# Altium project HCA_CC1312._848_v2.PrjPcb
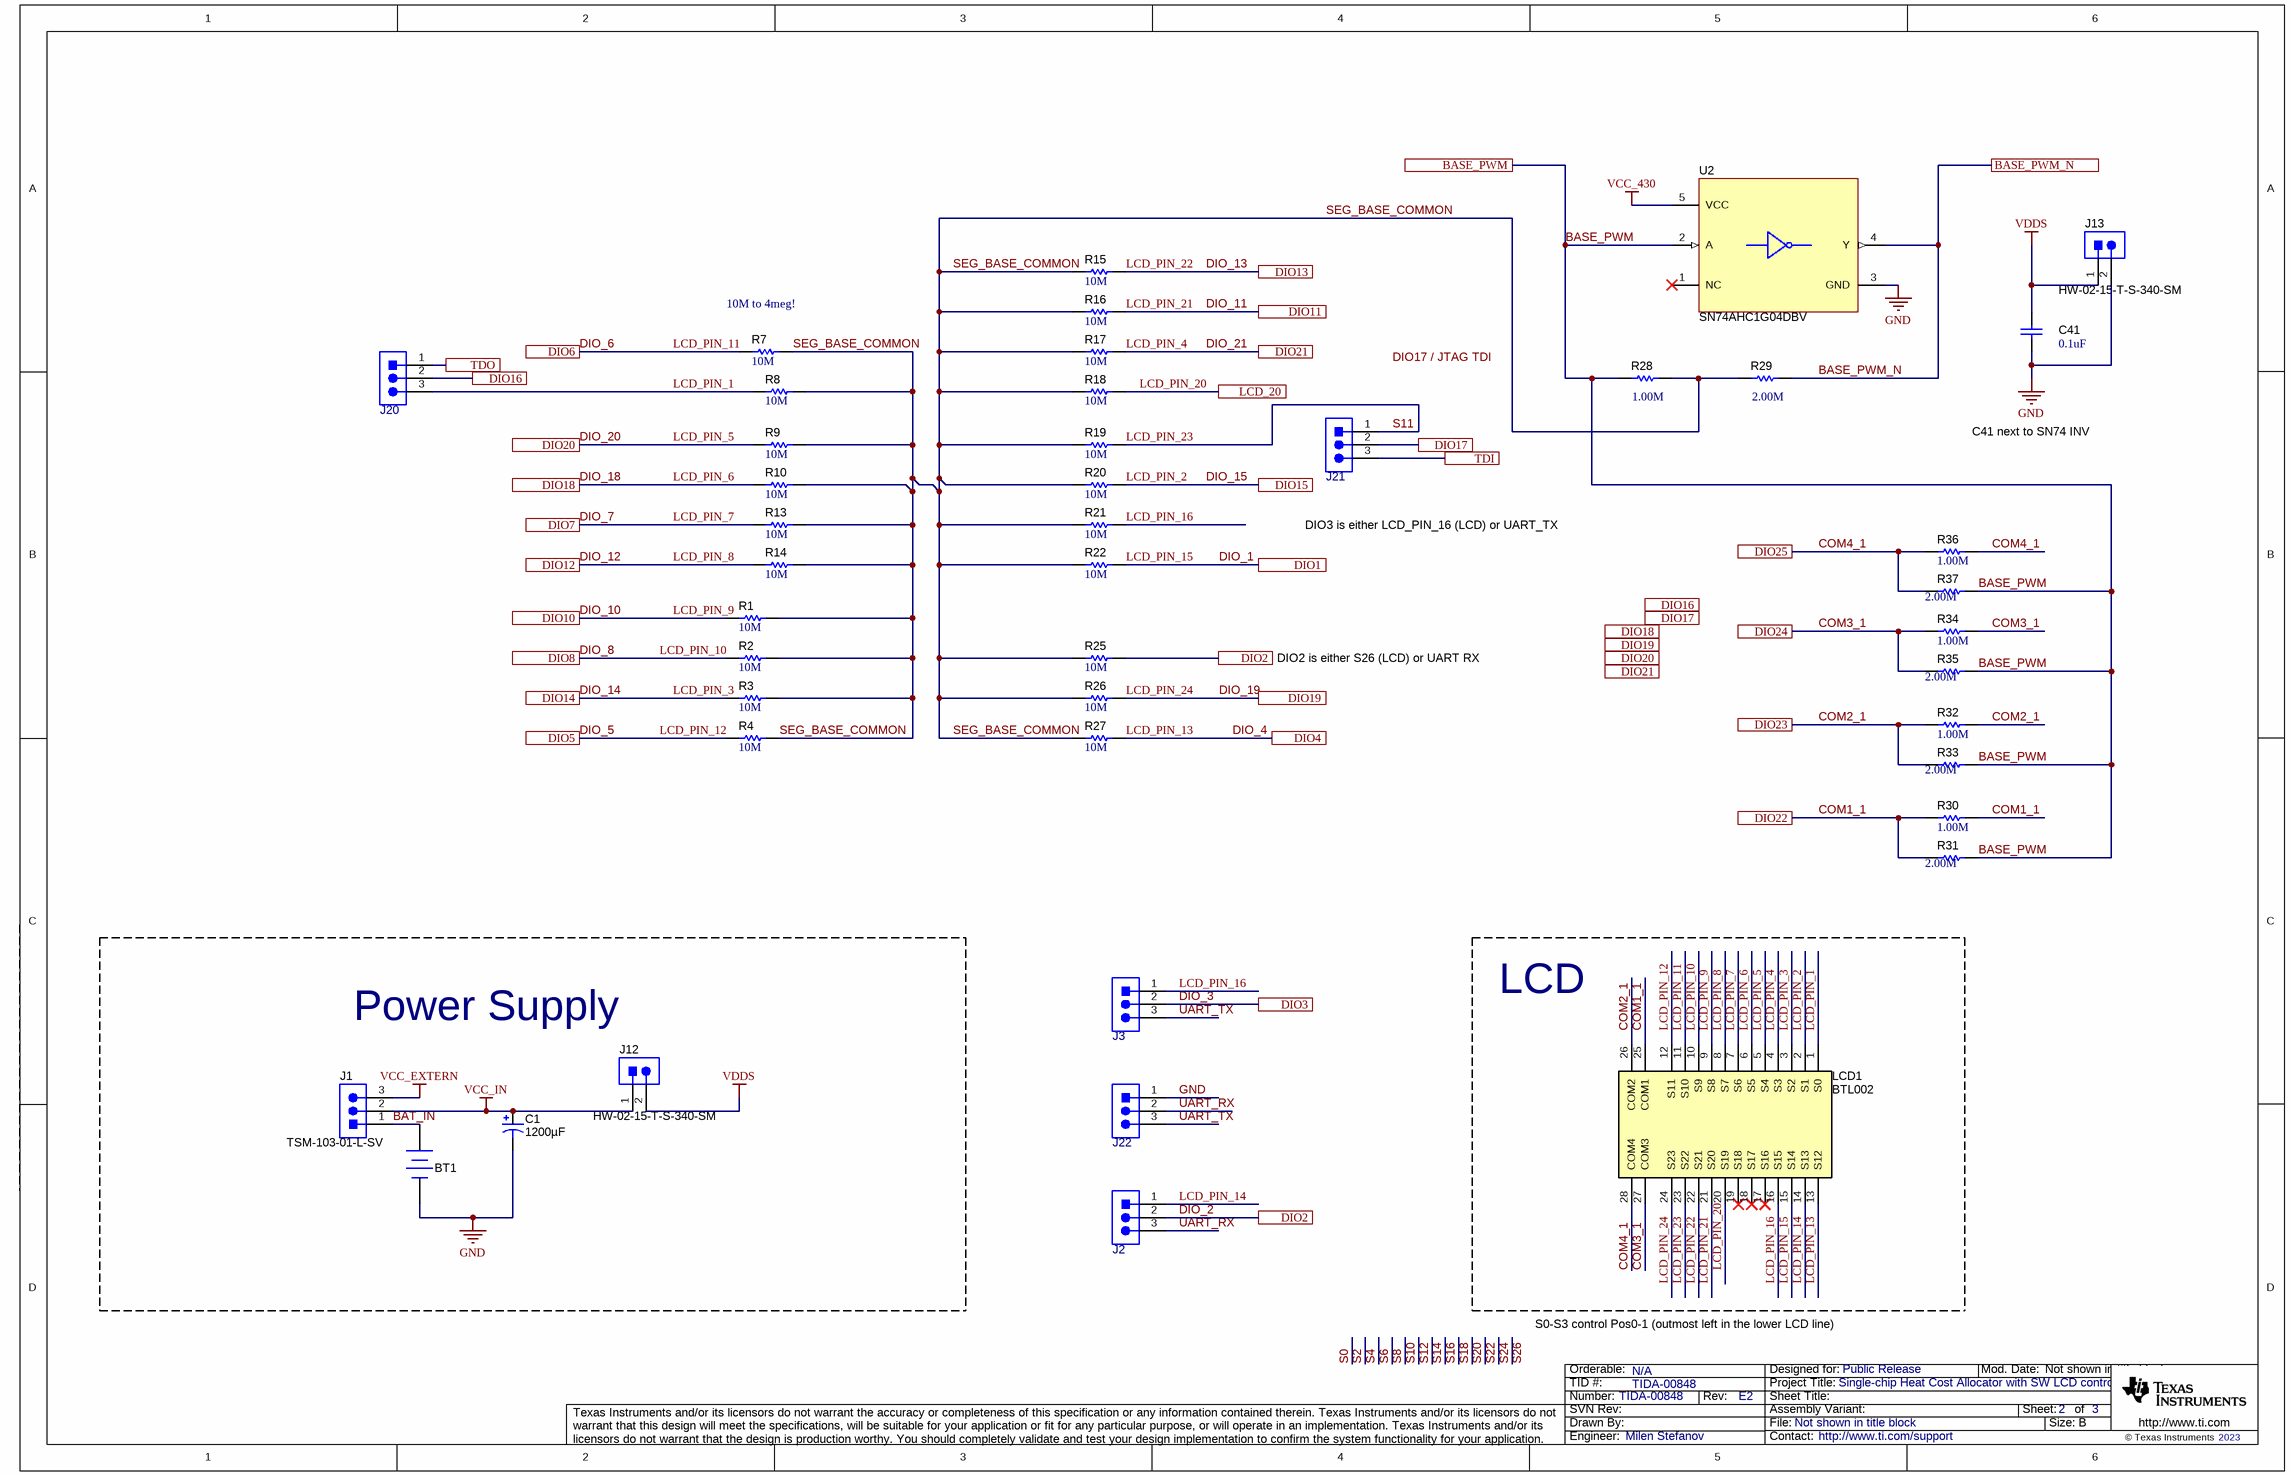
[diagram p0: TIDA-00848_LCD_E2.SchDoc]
CopyrightYear: 2023; EVM_Orderable: N/A; PCB_Layout: Milen Stefanov; PCB_Rev: E2; PRJ_Customer: Public Release; PRJ_Engineer: Milen Stefanov; PRJ_Number: TIDA-00848; PRJ_Title: Single-chip Heat Cost Allocator with SW LCD control; SCH_Rev: E2; TechSupport: http://www.ti.com/support; TID: TIDA-00848
4 sheets, 102 parts. Net scope: flat (ports and power ports of the same name join across sheets).
Board file: TIDA-00848_E2.PcbDoc
Sheets:
  TIDA-00848_LCD_E2.SchDoc
  TIDA-00848__Hardware_E2.SchDoc
  TIDA-00848_RF_E2.SchDoc
  TIDA-00848-CoverSheet_E2.SchDoc

## Sheet TIDA-00848_LCD_E2.SchDoc
size 431 x 279 mm; Date: Not shown in title block; ApprovedBy: Not shown in title block; CheckedBy: Not shown in title block; Author: Not shown in title block; CompanyName: Not shown in title block; Engineer: Not shown in title block; Organization: Not shown in title block; Address1: Not shown in title block; Address2: Not shown in title block; Address3: Not shown in title block; Address4: Not shown in title block; DocumentNumber: 1; Revision: Use project parameter SCH_Rev; SheetNumber: 2; SheetTotal: 3; PageSetup: Record=PageOptions¦CenterHorizontal=True¦CenterVertical=True¦PrintScale=0.62¦XCorrection=1.00¦YCorrection=1.00¦PrintKind=0¦BorderSize=5000000¦LeftOffset=0¦BottomOffset=0¦Orientation=2¦PaperLength=2794¦PaperWidth=2159¦Scale=100¦PaperSource=7¦PrintQuality=600¦MediaType=1¦DitherType=10¦PrintScaleMode=1¦PaperKind=8 1/2x11¦PaperIndex=1

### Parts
BT1  1010  [BAT_1010]  (value not drawn)
C1  ValueDisplayed: 1200µF  [CAPPR5-10X20]  (hidden comment: EEUFM1A122)
C41  ValueDisplayed: 0.1uF  [0402]  (hidden comment: CMP-0006607-2)
J1  TSM-103-01-L-SV  [Samtec_TSM-103-01-X-SV]
J2  TSW-103-07-G-S  [TSW-103-07-G-S]  (value not drawn)
J3  TSW-103-07-G-S  [TSW-103-07-G-S]  (value not drawn)
J12  HW-02-15-T-S-340-SM  [Samtec_HW-02-15-X-S-340-SM]
J13  HW-02-15-T-S-340-SM  [Samtec_HW-02-15-X-S-340-SM]
J20  TSW-103-07-G-S  [TSW-103-07-G-S]  (value not drawn)
J21  TSW-103-07-G-S  [TSW-103-07-G-S]  (value not drawn)
J22  TSW-103-07-G-S  [TSW-103-07-G-S]  (value not drawn)
LCD1  BTL002  [TI_BTL002]
R1  ValueDisplayed: 10M  [0402]  (hidden comment: CMP-0026826-2)
R2  ValueDisplayed: 10M  [0402]  (hidden comment: CMP-0026826-2)
R3  ValueDisplayed: 10M  [0402]  (hidden comment: CMP-0026826-2)
R4  ValueDisplayed: 10M  [0402]  (hidden comment: CMP-0026826-2)
R7  ValueDisplayed: 10M  [0402]  (hidden comment: CMP-0026826-2)
R8  ValueDisplayed: 10M  [0402]  (hidden comment: CMP-0026826-2)
R9  ValueDisplayed: 10M  [0402]  (hidden comment: CMP-0026826-2)
R10  ValueDisplayed: 10M  [0402]  (hidden comment: CMP-0026826-2)
R13  ValueDisplayed: 10M  [0402]  (hidden comment: CMP-0026826-2)
R14  ValueDisplayed: 10M  [0402]  (hidden comment: CMP-0026826-2)
R15  ValueDisplayed: 10M  [0402]  (hidden comment: CMP-0026826-2)
R16  ValueDisplayed: 10M  [0402]  (hidden comment: CMP-0026826-2)
R17  ValueDisplayed: 10M  [0402]  (hidden comment: CMP-0026826-2)
R18  ValueDisplayed: 10M  [0402]  (hidden comment: CMP-0026826-2)
R19  ValueDisplayed: 10M  [0402]  (hidden comment: CMP-0026826-2)
R20  ValueDisplayed: 10M  [0402]  (hidden comment: CMP-0026826-2)
R21  ValueDisplayed: 10M  [0402]  (hidden comment: CMP-0026826-2)
R22  ValueDisplayed: 10M  [0402]  (hidden comment: CMP-0026826-2)
R25  ValueDisplayed: 10M  [0402]  (hidden comment: CMP-0026826-2)
R26  ValueDisplayed: 10M  [0402]  (hidden comment: CMP-0026826-2)
R27  ValueDisplayed: 10M  [0402]  (hidden comment: CMP-0026826-2)
R28  ValueDisplayed: 1.00M  [0402]  (hidden comment: CRCW04021M00FKED)
R29  ValueDisplayed: 2.00M  [0402]  (hidden comment: CRCW04022M00FKED)
R30  ValueDisplayed: 1.00M  [0402S]  (hidden comment: CRCW04021M00FKED)
R31  ValueDisplayed: 2.00M  [0402S]  (hidden comment: CRCW04022M00FKED)
R32  ValueDisplayed: 1.00M  [0402S]  (hidden comment: CRCW04021M00FKED)
R33  ValueDisplayed: 2.00M  [0402S]  (hidden comment: CRCW04022M00FKED)
R34  ValueDisplayed: 1.00M  [0402S]  (hidden comment: CRCW04021M00FKED)
R35  ValueDisplayed: 2.00M  [0402S]  (hidden comment: CRCW04022M00FKED)
R36  ValueDisplayed: 1.00M  [0402S]  (hidden comment: CRCW04021M00FKED)
R37  ValueDisplayed: 2.00M  [0402S]  (hidden comment: CRCW04022M00FKED)
U2  SN74AHC1G04DBV  [DBV0005A_M]

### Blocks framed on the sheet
Power Supply: BT1 C1 J1 J12
LCD: LCD1

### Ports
BASE_PWM, BASE_PWM_N, DIO1, DIO2, DIO3, DIO4, DIO5, DIO6, DIO7, DIO8, DIO10, DIO11, DIO12, DIO13, DIO14, DIO15, DIO16, DIO17, DIO18, DIO19, DIO20, DIO21, DIO22, DIO23, DIO24, DIO25, LCD_20, TDI, TDO

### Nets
GND: BT1.2(-) C1.2(-) C41.2 J13.2 J22.1 U2.3(GND)
VCC_430: U2.5(VCC)
VCC_EXTERN: J1.3
VCC_IN: C1.1(+) J1.2 J12.1
VDDS: C41.1 J12.2 J13.1
BASE_PWM: R28.1 R31.2 R33.2 R35.2 R37.2 U2.2(A) ; port BASE_PWM
BASE_PWM_N: R29.2 U2.4(Y) ; port BASE_PWM_N
BAT_IN: BT1.1(+) J1.1
COM1_1: LCD1.25(COM1) R30.1 R30.2 R31.1 ; port DIO22
COM2_1: LCD1.26(COM2) R32.1 R32.2 R33.1 ; port DIO23
COM3_1: LCD1.27(COM3) R34.1 R34.2 R35.1 ; port DIO24
COM4_1: LCD1.28(COM4) R36.1 R36.2 R37.1 ; port DIO25
DIO_1: LCD1.15(S14) R22.2 ; port DIO1  [also labelled LCD_PIN_15]
DIO_2: J2.2 R25.2 ; port DIO2
DIO_3: J3.2 ; port DIO3
DIO_4: LCD1.13(S12) R27.2 ; port DIO4  [also labelled LCD_PIN_13]
DIO_5: LCD1.12(S11) R4.1 ; port DIO5  [also labelled LCD_PIN_12]
DIO_6: LCD1.11(S10) R7.1 ; port DIO6  [also labelled LCD_PIN_11]
DIO_7: LCD1.7(S6) R13.1 ; port DIO7  [also labelled LCD_PIN_7]
DIO_8: LCD1.10(S9) R2.1 ; port DIO8  [also labelled LCD_PIN_10]
DIO_10: LCD1.9(S8) R1.1 ; port DIO10  [also labelled LCD_PIN_9]
DIO_11: LCD1.21(S20) R16.2 ; port DIO11  [also labelled LCD_PIN_21]
DIO_12: LCD1.8(S7) R14.1 ; port DIO12  [also labelled LCD_PIN_8]
DIO_13: LCD1.22(S21) R15.2 ; port DIO13  [also labelled LCD_PIN_22]
DIO_14: LCD1.3(S2) R3.1 ; port DIO14  [also labelled LCD_PIN_3]
DIO_15: LCD1.2(S1) R20.2 ; port DIO15  [also labelled LCD_PIN_2]
DIO_18: LCD1.6(S5) R10.1 ; port DIO18  [also labelled LCD_PIN_6]
DIO_19: LCD1.24(S23) R26.2 ; port DIO19  [also labelled LCD_PIN_24]
DIO_20: LCD1.5(S4) R9.1 ; port DIO20  [also labelled LCD_PIN_5]
DIO_21: LCD1.4(S3) R17.2 ; port DIO21  [also labelled LCD_PIN_4]
JTAG_TDI: J21.2 ; port DIO17
JTAG_TDO: J20.2 ; port DIO16
LCD_PIN_1: J20.3 LCD1.1(S0) R8.1
LCD_PIN_14: J2.1 LCD1.14(S13)
LCD_PIN_16: J3.1 LCD1.16(S15) R21.2
LCD_PIN_20: LCD1.20(S19) R18.2 ; port LCD_20
LCD_PIN_23: J21.1 LCD1.23(S22) R19.2  [also labelled S11]
SEG_BASE_COMMON: R1.2 R2.2 R3.2 R4.2 R7.2 R8.2 R9.2 R10.2 R13.2 R14.2 R15.1 R16.1 R17.1 R18.1 R19.1 R20.1 R21.1 R22.1 R25.1 R26.1 R27.1 R28.2 R29.1
TDI: J21.3 ; port TDI
TDO: J20.1 ; port TDO
UART_RX: J2.3 J22.2
UART_TX: J3.3 J22.3

Not connected (* = marked no-connect by the designer): LCD1 17(S16)* 18(S17)* 19(S18)*; U2 1(NC)*

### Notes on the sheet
- (near R7) 10M to 4meg!
- C41 next to SN74 INV
- DIO3 is either LCD_PIN_16 (LCD) or UART_TX
- DIO2 is either S26 (LCD) or UART RX
- S0-S3 control Pos0-1 (outmost left in the lower LCD line)
- Labels drawn without touching a wire or pin: DIO17 / JTAG TDI, S26

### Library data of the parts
BT1 = 1010: Battery Holder, Nylon, CR2, SMT; Manufacturer: Keystone
C1 = EEUFM1A122: CAP, AL, 1200 µF, 10 V, +/- 20%, TH; Manufacturer: Panasonic; Polarized: Y; CompType: Capacitor; Value: 1200uF; U/M: EA; Cap_F: 0.0012; Tolerance_%: 20; Value1: Unknown; VDC_V: 10; Value2: 10V; TaMin_C: -40; TaMax_C: 105; Cap_Case: 10x20
C41 = CMP-0006607-2: CAP, CERM, 0.1 uF, 25 V, +/- 10%, X5R, 0402; PartNumber: GRM155R61E104KA87D; Manufacturer: MuRata; Polarized: N; Value: 0.1uF; U/M: EA; Cap_F: 100nF; Value1: Unknown; VDC_V: 25V; TaMin_C: -55°C; TaMax_C: 85°C; SizeAreaWB_mm2: 3; SizeZ_mm: 0.6; SizeX_mm: 1; SizeY_mm: 0.5; AEC Category: Q200
J1 = TSM-103-01-L-SV: Header, 100mil, 3x1, Gold, SMT; Manufacturer: Samtec; SymbolCreator: a0799628; U/M: EA
J2 J3 J20-J22 = TSW-103-07-G-S: Header, TH, 100mil, 3x1, Gold plated, 230 mil above insulator; Manufacturer: Samtec; SymbolCreator: a0799628; U/M: EA
J12 J13 = HW-02-15-T-S-340-SM: Header, 100mil, 2x1, Gold, SMD; Manufacturer: Samtec; SymbolCreator: a0412235; U/M: EA
LCD1 = CMP-0004933-1: LCD, 96 segments, 4-MUX, TH; Manufacturer: Texas Instruments
R1-R4 R7-R10 R13-R22 R25-R27 = CMP-0026826-2: RES, 10 M, 5%, 0.063 W, AEC-Q200 Grade 0, 0402; PartNumber: CRCW040210M0JNED; Manufacturer: Vishay-Dale; Value: 10Meg; Value_Code: 10M0; Power_W: 63mW; Value2: 0.063W; VDC_V: 50V; TempCo: 200 ppm/C; EIA_Code: E24; AEC Category: Q200; AEC Qualified: Y; AEC Grade: 0; SizeX_mm: 1; SizeY_mm: 0.5; SizeZ_mm: 0.6
R28 = CMP-0026100-2: RES, 1.00 M, 1%, 0.063 W, AEC-Q200 Grade 0, 0402; Manufacturer: Vishay-Dale; Value: 1.00Meg; Res_ohm: 1M; Power_W: 63mW; VDC_V: 50V; TempCo: 100 ppm/C; AEC Qualified: Y; SizeZ_mm: 0.6; Value_Code: 1M00; EIA_Code: E96; SizeX_mm: 1; SizeY_mm: 0.5; Value2: 0.063W; AEC Category: Q200; AEC Grade: 0
R29 = CMP-0026245-2: RES, 2.00 M, 1%, 0.063 W, AEC-Q200 Grade 0, 0402; Manufacturer: Vishay-Dale; Res_ohm: 2M; Power_W: 63mW; VDC_V: 50V; TempCo: 100 ppm/C; AEC Qualified: Y; SizeZ_mm: 0.6; Value: 2.00Meg; Value_Code: 2M00; EIA_Code: E96; SizeX_mm: 1; SizeY_mm: 0.5; Value2: 0.063W; AEC Category: Q200; AEC Grade: 0
R30 R32 R34 R36 = CMP-0026100-2: RES, 1.00 M, 1%, 0.063 W, AEC-Q200 Grade 0, 0402; Manufacturer: Vishay-Dale; Value: 1.00Meg; Res_ohm: 1M; Value_Code: 1M00; Power_W: 63mW; Value2: 0.063W; VDC_V: 50V; TempCo: 100 ppm/C; EIA_Code: E96; SizeX_mm: 1; SizeY_mm: 0.5; SizeZ_mm: 0.6; AEC Qualified: Y; AEC Category: Q200; AEC Grade: 0
R31 R33 R35 R37 = CMP-0026245-2: RES, 2.00 M, 1%, 0.063 W, AEC-Q200 Grade 0, 0402; Manufacturer: Vishay-Dale; Value: 2.00Meg; Res_ohm: 2M; Value_Code: 2M00; Power_W: 63mW; Value2: 0.063W; VDC_V: 50V; TempCo: 100 ppm/C; EIA_Code: E96; SizeX_mm: 1; SizeY_mm: 0.5; SizeZ_mm: 0.6; AEC Qualified: Y; AEC Category: Q200; AEC Grade: 0
U2 = SN74AHC1G04DBV: SINGLE SCHMITT-TRIGGER INVERTER GATE, DBV0005A; Manufacturer: Texas Instruments; SymbolCreator: a0411947; CompType: IC; U/M: EA

## Sheet TIDA-00848__Hardware_E2.SchDoc
size 431 x 279 mm; Date: Not shown in title block; ApprovedBy: Not shown in title block; CheckedBy: Not shown in title block; Author: Not shown in title block; CompanyName: Not shown in title block; Engineer: Not shown in title block; Organization: Not shown in title block; Address1: Not shown in title block; Address2: Not shown in title block; Address3: Not shown in title block; Address4: Not shown in title block; DocumentNumber: 1; Revision: Use project parameter SCH_Rev; SheetNumber: 3; SheetTotal: 3; PageSetup: Record=PageOptions¦CenterHorizontal=True¦CenterVertical=True¦PrintScale=1.00¦XCorrection=1.00¦YCorrection=1.00¦PrintKind=0¦BorderSize=5000000¦LeftOffset=0¦BottomOffset=0¦Orientation=2¦PaperLength=1000¦PaperWidth=1000¦Scale=100¦PaperSource=15¦PrintQuality=600¦MediaType=1¦DitherType=10¦PaperKind=Letter¦PrintScaleMode=1
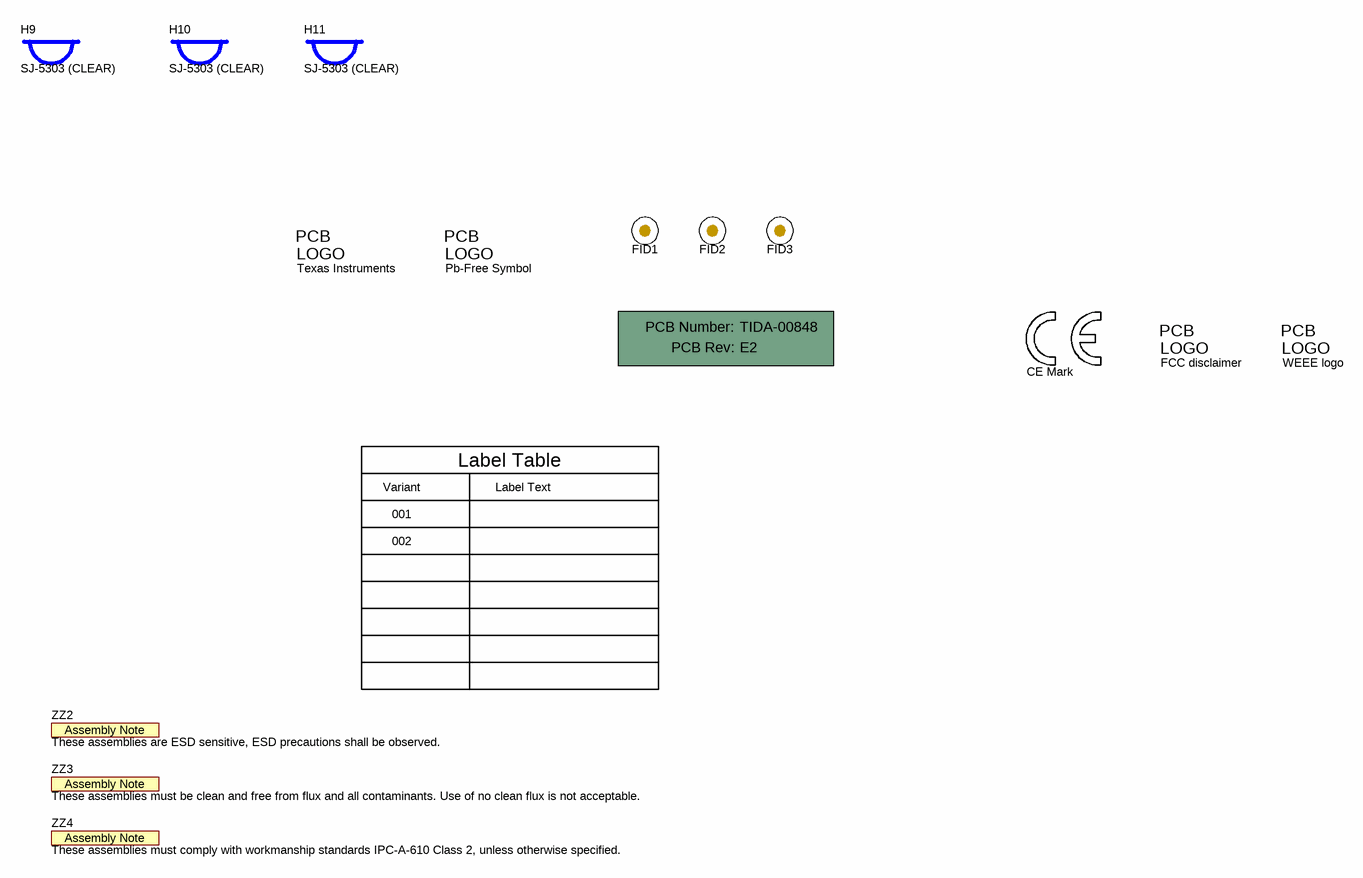
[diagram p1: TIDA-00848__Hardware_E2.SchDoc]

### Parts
(Parts that share a designator on the sheet are numbered #1, #2 ... from top to bottom, then left to right.)
!PCB?  Printed Circuit Board  (value not drawn)  (mechanical)
FID1  Fiducial  [Fiducial10-20]  (value not drawn)
FID2  Fiducial  [Fiducial10-20]  (value not drawn)
FID3  Fiducial  [Fiducial10-20]  (value not drawn)
H9  SJ-5303 (CLEAR)  [Bumpon_SJ5003Transparent]
H10  SJ-5303 (CLEAR)  [Bumpon_SJ5003Transparent]
H11  SJ-5303 (CLEAR)  [Bumpon_SJ5003Transparent]
Logo1  Texas Instruments  [TI_Symbol_Overlay_Small]  (no BOM)
Logo2  Pb-Free Symbol  [Pb-Free_Overlay_Small]  (no BOM)
Logo?#1  CE Mark  [CE_Mark_5mm]  (no BOM)
Logo?#2  FCC disclaimer  [FCC_disclaimer]  (no BOM)
Logo?#3  WEEE logo  [WEEE_Minimum]  (no BOM)
ZZ2  These assemblies are ESD sensitive, ESD precautions shall be observed.  [AssemblyNote]  (no BOM)
ZZ3  These assemblies must be clean and free from flux and all contaminants. Use of no clean flux is not acceptable.  [AssemblyNote]  (no BOM)
ZZ4  These assemblies must comply with workmanship standards IPC-A-610 Class 2, unless otherwise specified.  [AssemblyNote]  (no BOM)

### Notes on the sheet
- Variant
- Label Table
- Label Text
- 001
- 002

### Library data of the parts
!PCB? = CMP-0003618-2: Manufacturer: Any; PartNumber: TIDA-00848
FID1-FID3 = CMP-0077181-1: Fiducial mark.  There is nothing to buy or mount.
H9-H11 = SJ-5303 (CLEAR): Bumpon, Hemisphere, 0.44 X 0.20, Clear; Manufacturer: 3M; SymbolCreator: a0412235
Logo1 = TI_Logo: Texas Instrument Corporate Signature; SymbolCreator: codlsc
Logo2 = Pb-Free: SymbolCreator: a0412235
Logo?#1 = CMP-0074844-1: SymbolCreator: a0412235
Logo?#2 = CMP-0074847-1: FCC_disclaimer; Library Reference: Logo
Logo?#3 = CMP-0074769-1
ZZ2-ZZ4 = AssemblyNote: SymbolCreator: codlsc

## Sheet TIDA-00848_RF_E2.SchDoc
size 431 x 279 mm; Date: Not shown in title block; ApprovedBy: Not shown in title block; CheckedBy: Not shown in title block; Author: Not shown in title block; CompanyName: Not shown in title block; Engineer: Not shown in title block; Organization: Not shown in title block; Address1: Not shown in title block; Address2: Not shown in title block; Address3: Not shown in title block; Address4: Not shown in title block; DocumentNumber: 1; Revision: Use project parameter SCH_Rev; SheetNumber: 2; SheetTotal: 3; PageSetup: Record=PageOptions¦CenterHorizontal=True¦CenterVertical=True¦PrintScale=0.62¦XCorrection=1.00¦YCorrection=1.00¦PrintKind=0¦BorderSize=5000000¦LeftOffset=0¦BottomOffset=0¦Orientation=2¦PaperLength=2794¦PaperWidth=2159¦Scale=100¦PaperSource=7¦PrintQuality=600¦MediaType=1¦DitherType=10¦PrintScaleMode=1¦PaperKind=8 1/2x11¦PaperIndex=1
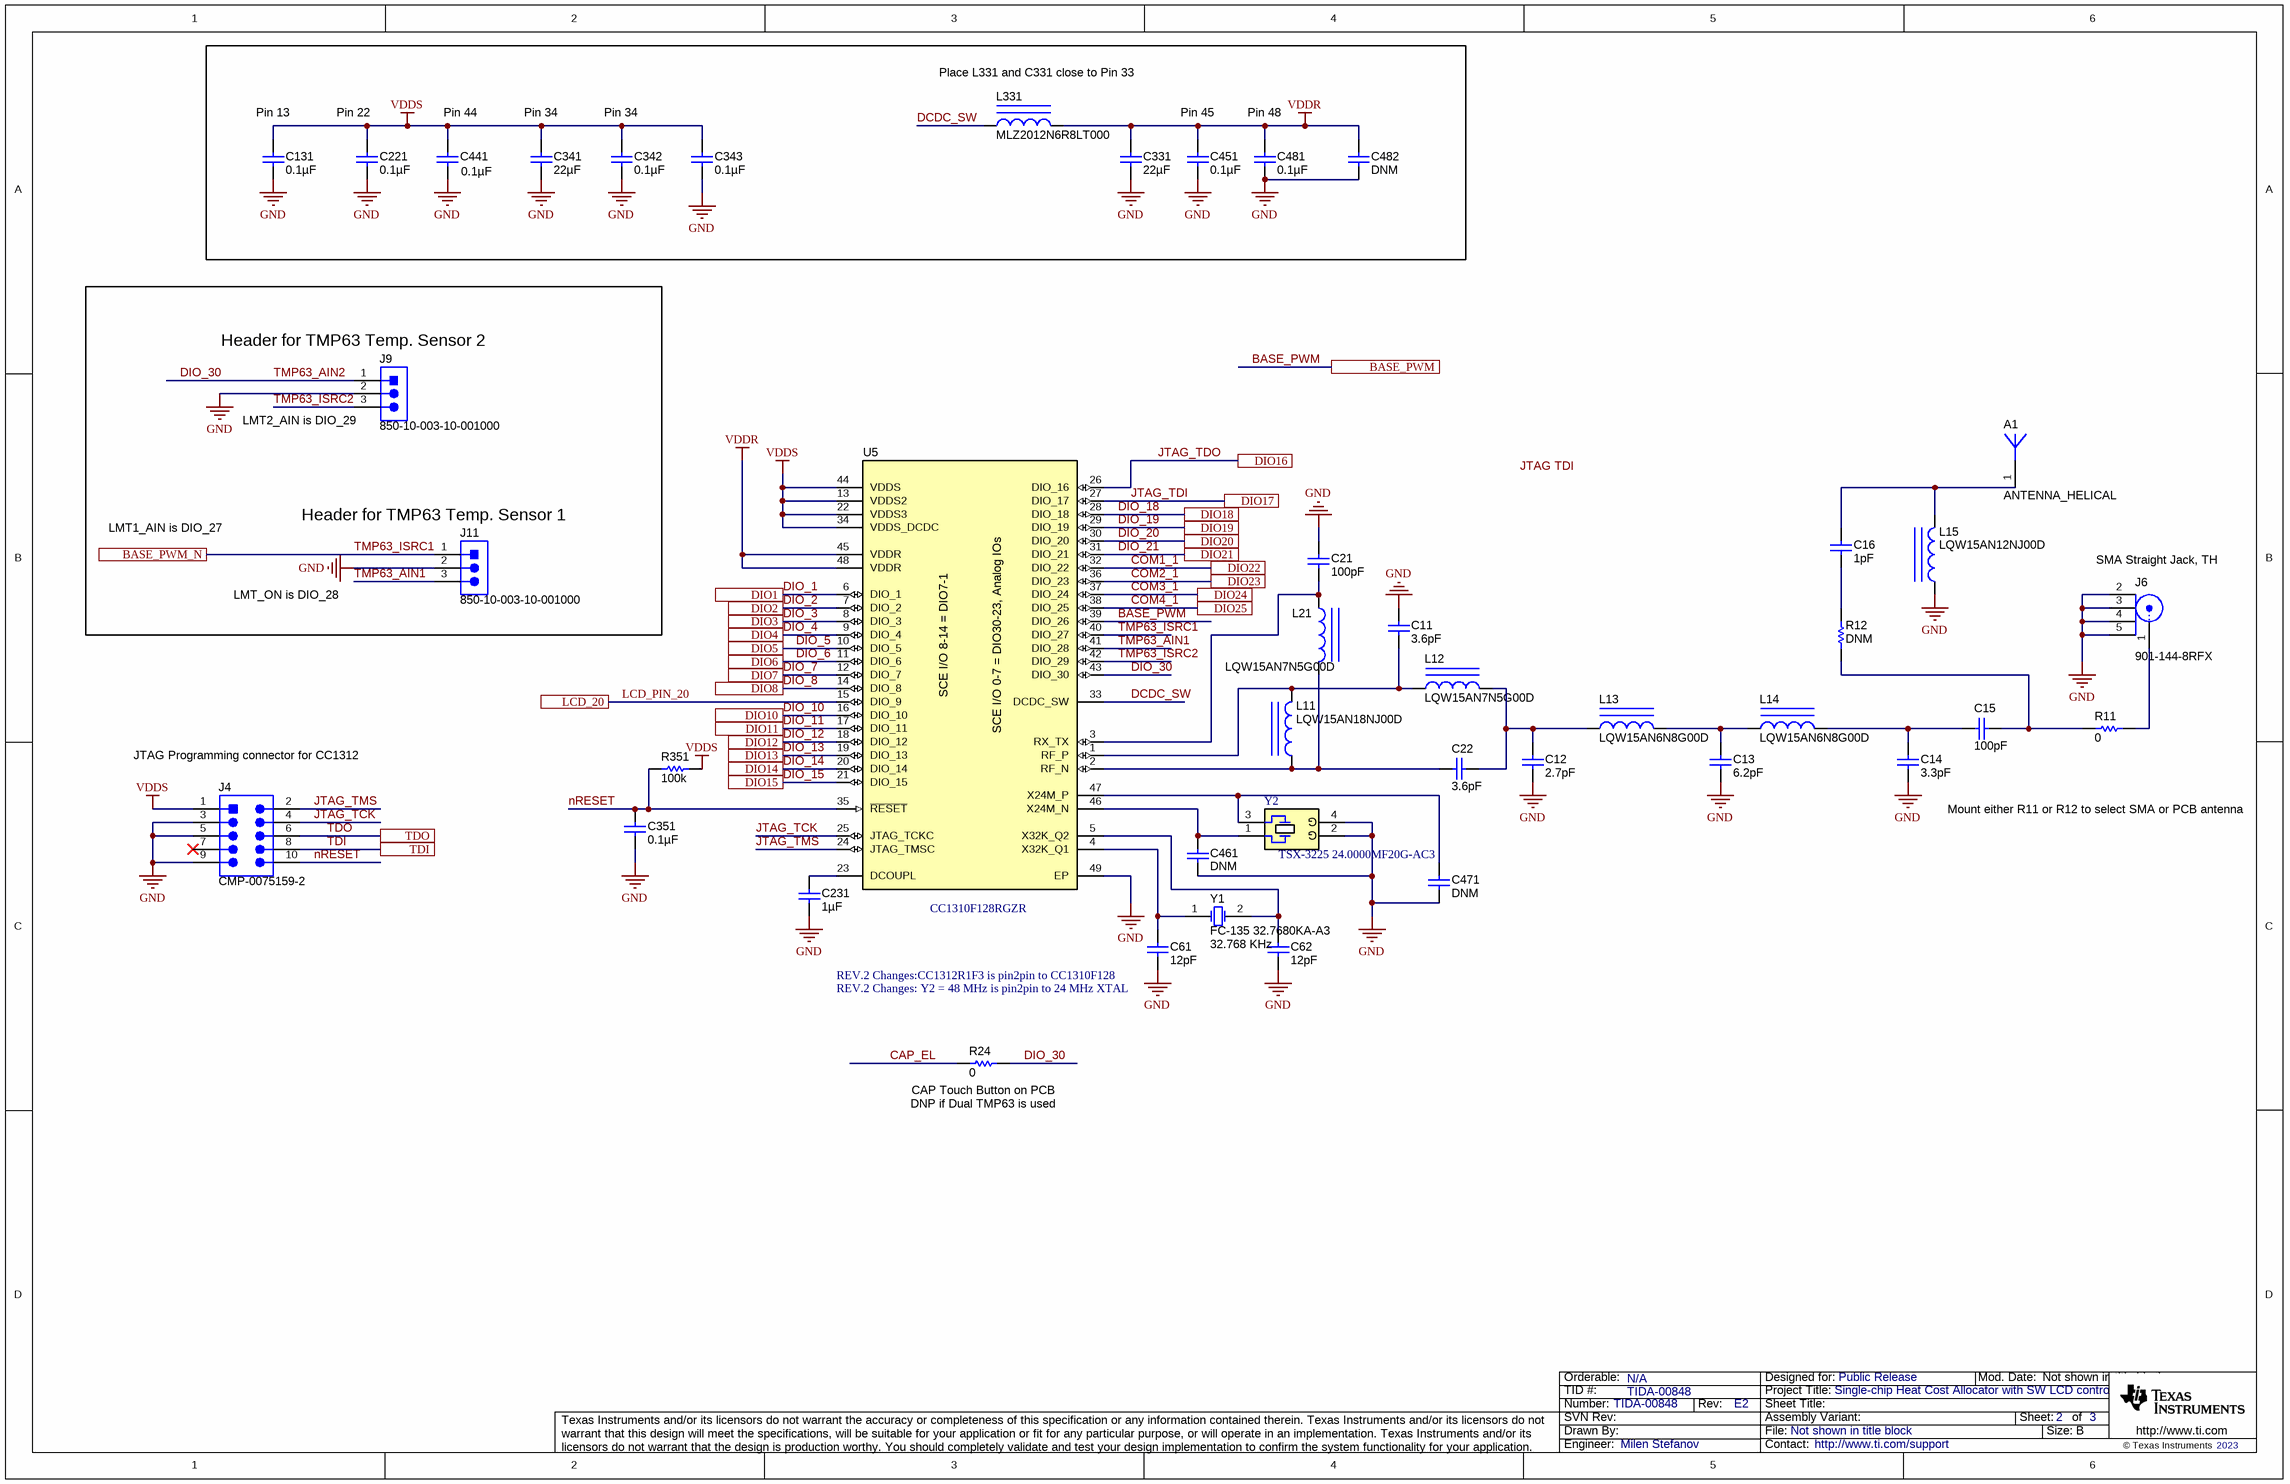
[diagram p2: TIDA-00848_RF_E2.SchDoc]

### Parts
A1  ANTENNA_HELICAL  [ANTENNA_HELICAL]  (net tie)
C11  ValueDisplayed: 3.6pF  [0402S]  (hidden comment: Comment)
C12  ValueDisplayed: 2.7pF  [0402S]  (hidden comment: GRM1555C1H2R7CA01D)
C13  ValueDisplayed: 6.2pF  [0402S]  (hidden comment: GRM1555C1H6R2CA01D)
C14  ValueDisplayed: 3.3pF  [0402S]  (hidden comment: GRM1555C1H3R3CA01D)
C15  ValueDisplayed: 100pF  [0402S]  (hidden comment: GRM1555C1H101JA01D)
C16  ValueDisplayed: 1pF  [0402S]  (hidden comment: GRM1555C1H1R0CA01D)
C21  ValueDisplayed: 100pF  [0402S]  (hidden comment: GRM1555C1H101JA01D)
C22  ValueDisplayed: 3.6pF  [0402S]  (hidden comment: GRM1555C1H3R6CA01D)
C61  ValueDisplayed: 12pF  [0402S]  (hidden comment: Comment)
C62  ValueDisplayed: 12pF  [0402S]  (hidden comment: GRM1555C1H120JA01D)
C131  ValueDisplayed: 0.1µF  [0402S]  (hidden comment: Comment)
C221  ValueDisplayed: 0.1µF  [0402S]  (hidden comment: Comment)
C231  ValueDisplayed: 1µF  [0402S]  (hidden comment: Comment)
C331  ValueDisplayed: 22µF  [0603S]  (hidden comment: GRM188R60J226MEA0J)
C341  ValueDisplayed: 22µF  [0603S]  (hidden comment: GRM188R60J226MEA0J)
C342  ValueDisplayed: 0.1µF  [0402S]  (hidden comment: GRM155R61E104KA87D)
C343  ValueDisplayed: 0.1µF  [0402S]  (hidden comment: GRM155R61E104KA87D)
C351  ValueDisplayed: 0.1µF  [0402S]  (hidden comment: GRM155R70J104KA01D)
C441  ValueDisplayed: 0.1µF  [0402S]  (hidden comment: GRM155R70J104KA01D)
C451  ValueDisplayed: 0.1µF  [0402S]  (hidden comment: GRM155R70J104KA01D)
C461  DNM  [0402S]
C471  DNM  [0402S]
C481  ValueDisplayed: 0.1µF  [0402S]  (hidden comment: GRM155R70J104KA01D)
C482  ValueDisplayed: DNM  [0402S]  (hidden comment: GRM155R70J104KA01D)
J4  CMP-0075159-2  [Gradconn_BB02-BS101-xAx-025B00]
J6  901-144-8RFX  PackageReference: SMA Straight Jack, TH  [Amphenol_901-144-8RFX]
J9  850-10-003-10-001000  [Mill-Max_850-10-003-10-001000]
J11  850-10-003-10-001000  [Mill-Max_850-10-003-10-001000]
L11  LQW15AN18NJ00D  [LQW15A_00_10]
L12  LQW15AN7N5G00D  [LQW15A_00_10]
L13  LQW15AN6N8G00D  [LQW15A_00_10]
L14  LQW15AN6N8G00D  [LQW15A_00_10]
L15  LQW15AN12NJ00D  [LQW15A_00_10]
L21  LQW15AN7N5G00D  [LQW15A_00_10]
L331  MLZ2012N6R8LT000  [0805_145]
R11  ValueDisplayed: 0  [0402S]  (hidden comment: CRCW04020000Z0ED)
R12  ValueDisplayed: DNM  [0402S]  (hidden comment: Comment)
R24  ValueDisplayed: 0  [0402S]  (hidden comment: CRCW04020000Z0ED)
R351  ValueDisplayed: 100k  [0402S]  (hidden comment: ERJ-2RKF1003X)
U5  PartNumber: CC1310F128RGZR  [RGZ0048A]  (hidden comment: CMP-0076688-3)
Y1  FC-135 32.7680KA-A3  Frequency: 32.768 KHz  [Epson_FC-135]
Y2  PartNumber: TSX-3225 24.0000MF20G-AC3  [EPSON_TSX-3225]  (hidden comment: CMP-0004609-3)

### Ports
BASE_PWM, BASE_PWM_N, DIO1, DIO2, DIO3, DIO4, DIO5, DIO6, DIO7, DIO8, DIO10, DIO11, DIO12, DIO13, DIO14, DIO15, DIO16, DIO17, DIO18, DIO19, DIO20, DIO21, DIO22, DIO23, DIO24, DIO25, LCD_20, TDI, TDO

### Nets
GND: C11.1 C12.2 C13.2 C14.2 C21.1 C61.2 C62.2 C131.2 C221.2 C231.2 C331.2 C341.2 C342.2 C343.2 C351.2 C441.2 C451.2 C461.2 C471.2 C481.2 C482.2 J4.3 J4.5 J4.9 J6.2 J6.3 J6.4 J6.5 J9.2 J11.2 L15.1 U5.49(EP) Y2.2(GND) Y2.4(GND)
VDDR: C331.1 C451.1 C481.1 C482.1 L331.2 U5.45(VDDR) U5.48(VDDR)
VDDS: C131.1 C221.1 C341.1 C342.1 C343.1 C441.1 J4.1 R351.2 U5.13(VDDS2) U5.22(VDDS3) U5.34(VDDS_DCDC) U5.44(VDDS)
BASE_PWM: U5.39(DIO_26) ; port BASE_PWM
CAP_EL: R24.1
COM1_1: U5.32(DIO_22) ; port DIO22
COM2_1: U5.36(DIO_23) ; port DIO23
COM3_1: U5.37(DIO_24) ; port DIO24
COM4_1: U5.38(DIO_25) ; port DIO25
DCDC_SW: L331.1 U5.33(DCDC_SW)
DIO_1: U5.6(DIO_1) ; port DIO1
DIO_2: U5.7(DIO_2) ; port DIO2
DIO_3: U5.8(DIO_3) ; port DIO3
DIO_4: U5.9(DIO_4) ; port DIO4
DIO_5: U5.10(DIO_5) ; port DIO5
DIO_6: U5.11(DIO_6) ; port DIO6
DIO_7: U5.12(DIO_7) ; port DIO7
DIO_8: U5.14(DIO_8) ; port DIO8
DIO_10: U5.16(DIO_10) ; port DIO10
DIO_11: U5.17(DIO_11) ; port DIO11
DIO_12: U5.18(DIO_12) ; port DIO12
DIO_13: U5.19(DIO_13) ; port DIO13
DIO_14: U5.20(DIO_14) ; port DIO14
DIO_15: U5.21(DIO_15) ; port DIO15
DIO_18: U5.28(DIO_18) ; port DIO18
DIO_19: U5.29(DIO_19) ; port DIO19
DIO_20: U5.30(DIO_20) ; port DIO20
DIO_21: U5.31(DIO_21) ; port DIO21
DIO_30: J9.1 R24.2 U5.43(DIO_30)  [also labelled TMP63_AIN2]
JTAG_TCK: J4.4 U5.25(JTAG_TCKC)
JTAG_TDI: U5.27(DIO_17) ; port DIO17
JTAG_TDO: U5.26(DIO_16) ; port DIO16
JTAG_TMS: J4.2 U5.24(JTAG_TMSC)
LCD_PIN_20: U5.15(DIO_9) ; port LCD_20
nRESET: C351.1 J4.10 R351.1 U5.35(~{RESET})
TDI: J4.8 ; port TDI
TDO: J4.6 ; port TDO
TMP63_AIN1: J11.3 U5.41(DIO_28)
TMP63_ISRC1: J11.1 U5.40(DIO_27) ; port BASE_PWM_N  [project net BASE_PWM_N]
TMP63_ISRC2: J9.3 U5.42(DIO_29)
NetA1_1: A1.1 C16.1 L15.2
NetC11_2: C11.2 L11.2 L12.1 U5.1(RF_P)
NetC12_1: C12.1 C22.2 L12.2 L13.1
NetC13_1: C13.1 L13.2 L14.1
NetC14_1: C14.1 C15.1 L14.2
NetC15_2: C15.2 R11.1 R12.1
NetC16_2: C16.2 R12.2
NetC21_2: C21.2 L21.1 U5.3(RX_TX)
NetC22_1: C22.1 L11.1 L21.2 U5.2(RF_N)
NetC61_1: C61.1 U5.4(X32K_Q1) Y1.1(OSC1)
NetC62_1: C62.1 U5.5(X32K_Q2) Y1.2(OSC2)
NetC231_1: C231.1 U5.23(DCOUPL)
NetC461_1: C461.1 U5.46(X24M_N) Y2.1
NetC471_1: C471.1 U5.47(X24M_P) Y2.3
NetJ6_1: J6.1 R11.2

Not connected (* = marked no-connect by the designer): J4 7*

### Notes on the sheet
- Place L331 and C331 close to Pin 33
- (near C131) Pin 13
- (near C221) Pin 22
- (near C441) Pin 44
- (near C341) Pin 34
- (near C342) Pin 34
- (near C451) Pin 45
- (near C481) Pin 48
- (near J9) Header for TMP63 Temp. Sensor 2
- (near J9) LMT2_AIN is DIO_29
- LMT1_AIN is DIO_27
- (near J11) Header for TMP63 Temp. Sensor 1
- LMT_ON is DIO_28
- (near U5) SCE I/O 8-14 = DIO7-1
- (near U5) SCE I/O 0-7 = DIO30-23, Analog IOs
- (near J4) JTAG Programming connector for CC1312
- (near C14) Mount either R11 or R12 to select SMA or PCB antenna
- (near C61) REV.2 Changes:CC1312R1F3 is pin2pin to CC1310F128
- (near C61) REV.2 Changes: Y2 = 48 MHz is pin2pin to 24 MHz XTAL
- (near R24) CAP Touch Button on PCB
- (near R24) DNP if Dual TMP63 is used
- Labels drawn without touching a wire or pin: JTAG TDI

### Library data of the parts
A1 = ANTENNA_HELICAL: PCB Antenna. There is nothing to buy or mount.; SymbolCreator: Altium
C11 C22 = GRM1555C1H3R6CA01D: CAP, CERM, 3.6 pF, 50 V, +/- 5%, C0G/NP0, 0402; Manufacturer: MuRata; Polarized: N; CompType: Capacitor; Value: 3.6pF; U/M: EA; Cap_F: 0.0000000000036; Tolerance_%: 5; Value1: Unknown; VDC_V: 50; Value2: 50V; TaMin_C: -55; TaMax_C: 125; Cap_Case: 0402
C12 = GRM1555C1H2R7CA01D: CAP, CERM, 2.7 pF, 50 V, +/- 5%, C0G/NP0, 0402; Manufacturer: MuRata; Polarized: N; CompType: Capacitor; Value: 2.7pF; U/M: EA; Cap_F: 0.0000000000027; Tolerance_%: 5; Value1: Unknown; VDC_V: 50; Value2: 50V; TaMin_C: -55; TaMax_C: 125; Cap_Case: 0402
C13 = GRM1555C1H6R2CA01D: CAP, CERM, 6.2 pF, 50 V, +/- 5%, C0G/NP0, 0402; Manufacturer: MuRata; Polarized: N; CompType: Capacitor; Value: 6.2pF; U/M: EA; Cap_F: 0.0000000000062; Tolerance_%: 5; Value1: Unknown; VDC_V: 50; Value2: 50V; TaMin_C: -55; TaMax_C: 125; Cap_Case: 0402
C14 = GRM1555C1H3R3CA01D: CAP, CERM, 3.3 pF, 50 V, +/- 5%, C0G/NP0, 0402; Manufacturer: MuRata; Polarized: N; CompType: Capacitor; Value: 3.3pF; U/M: EA; Cap_F: 0.0000000000033; Tolerance_%: 5; Value1: Unknown; VDC_V: 50; Value2: 50V; TaMin_C: -55; TaMax_C: 125; Cap_Case: 0402
C15 C21 = GRM1555C1H101JA01D: CAP, CERM, 100 pF, 50 V, +/- 5%, C0G/NP0, 0402; Manufacturer: MuRata; Polarized: N; CompType: Capacitor; Value: 100pF; U/M: EA; Cap_F: 0.0000000001; Tolerance_%: 5; Value1: Unknown; VDC_V: 50; Value2: 50V; TaMin_C: -55; TaMax_C: 125; Cap_Case: 0402
C16 = GRM1555C1H1R0CA01D: CAP, CERM, 1 pF, 50 V, +/- 5%, C0G/NP0, 0402; Manufacturer: MuRata; Polarized: N; CompType: Capacitor; Value: 1pF; U/M: EA; Cap_F: 0.000000000001; Tolerance_%: 5; Value1: Unknown; VDC_V: 50; Value2: 50V; TaMin_C: -55; TaMax_C: 125; Cap_Case: 0402
C61 C62 C461 C471 = GRM1555C1H120JA01D: CAP, CERM, 12 pF, 50 V, +/- 5%, C0G/NP0, 0402; Manufacturer: MuRata; Polarized: N; CompType: Capacitor; Value: 12pF; U/M: EA; Cap_F: 0.000000000012; Tolerance_%: 5; Value1: Unknown; VDC_V: 50; Value2: 50V; TaMin_C: -55; TaMax_C: 125; Cap_Case: 0402
C131 C221 C351 C441 C451 C481 C482 = GRM155R70J104KA01D: CAP, CERM, 0.1 µF, 6.3 V, +/- 10%, X7R, 0402; Manufacturer: MuRata; Polarized: N; CompType: Capacitor; Value: 0.1uF; U/M: EA; Cap_F: 0.0000001; Tolerance_%: 10; Value1: Unknown; VDC_V: 6.3; Value2: 6.3V; TaMin_C: -55; TaMax_C: 125; Cap_Case: 0402
C231 = GRM155R61A105KE15D: CAP, CERM, 1 µF, 10 V, +/- 10%, X5R, 0402; Manufacturer: MuRata; Polarized: N; CompType: Capacitor; Value: 1uF; U/M: EA; Cap_F: 0.000001; Tolerance_%: 10; Value1: Unknown; Value2: 10V; TaMin_C: -55; TaMax_C: 85; Cap_Case: 0402
C331 C341 = GRM188R60J226MEA0J: CAP, CERM, 22 µF, 6.3 V, +/- 20%, X5R, 0603; Manufacturer: MuRata; Polarized: N; CompType: Capacitor; Value: 22uF; U/M: EA; Cap_F: 0.000022; Tolerance_%: 20; Value1: Unknown; VDC_V: 6.3; Value2: 6.3V; TaMin_C: -55; TaMax_C: 85; Cap_Case: 0603
C342 C343 = GRM155R61E104KA87D: CAP, CERM, 0.1 µF, 25 V, +/- 10%, X5R, 0402; Manufacturer: MuRata; Polarized: N; CompType: Capacitor; Value: 0.1uF; U/M: EA; Cap_F: 0.0000001; Tolerance_%: 10; Value1: Unknown; VDC_V: 25; Value2: 25V; TaMin_C: -55; TaMax_C: 85; Cap_Case: 0402
J4 = CMP-0075159-2: Header, 1.27mm, 5x2, SMT; PartNumber: BB02-BS101-KA8-025B00; Manufacturer: GradConn; Shrouded: N; Gender: Male; Row_Count: 2; RowSpacing_mm: 1.27; ContactFinish: Gold
J6 = 901-144-8RFX: SMA Straight Jack, Gold, 50 Ohm, TH; Manufacturer: Amphenol RF; SymbolCreator: X0208326; U/M: EA
J9 J11 = 850-10-003-10-001000: Header, 50mil, 3x1, Gold, TH; Manufacturer: Mill-Max; SymbolCreator: a0799628; U/M: EA
L11 = LQW15AN18NJ00D: Inductor, Wirewound, 18 nH, 0.37 A, 0.27 ohm, SMD; Manufacturer: MuRata; Value: 18nH; Ind_H: 18.0E-9; Imax_A: 0.37; DCR_ohm: 0.27; Value2: 0.37A
L12 L21 = LQW15AN7N5G00D: Inductor, Wirewound, 7.5 nH, 0.57 A, 0.13 ohm, SMD; Manufacturer: MuRata; Value: 7.5nH; Ind_H: 7.5E-9; Imax_A: 0.57; Irms: 0.57A @ C rise; DCR_ohm: 0.13; Value2: 0.57A
L13 L14 = LQW15AN6N8G00D: Inductor, Wirewound, 6.8 nH, 0.7 A, 0.09 ohm, SMD; Manufacturer: MuRata; Value: 6.8nH; Ind_H: 6.8E-9; Imax_A: 0.7; DCR_ohm: 0.09; Value2: 0.7A
L15 = LQW15AN12NJ00D: Inductor, Wirewound, 12 nH, 0.5 A, 0.14 ohm, SMD; Manufacturer: MuRata; Value: 12nH; Ind_H: 12.0E-9; Imax_A: 0.5; DCR_ohm: 0.14; Value2: 0.5A
L331 = MLZ2012N6R8LT000: Inductor, Multilayer, Ferrite, 6.8 µH, 0.11 A, 0.25 ohm, SMD; Manufacturer: TDK; Value: 6.8uH; Ind_H: 6.8E-6; ValueDisplayed: 6.8µH; Imax_A: 0.11; Irms: 0.55A @ 20C rise; Isat: 0.11A @ 50% inductance drop; DCR_ohm: 0.25; Value2: 0.11A
R11 R12 R24 = CRCW04020000Z0ED: RES, 0, 5%, 0.063 W, 0402; Manufacturer: Vishay-Dale; CompType: Resistor; Value: 0; Value_Code: 0000; Tolerance_%: 5; Power_W: 0.063; Value2: 0.063W; VDC_V: 50; TempCo: 200 ppm/C; EIA_Code: E24; U/M: EA
R351 = ERJ-2RKF1003X: RES, 100 k, 1%, 0.1 W, 0402; Manufacturer: Panasonic; CompType: Resistor; Value: 100k; Res_ohm: 100000; Tolerance_%: 1; Power_W: 0.1; Value2: 0.1W; VDC_V: 50; TempCo: 100 ppm/C; EIA_Code: E96; U/M: EA
U5 = CMP-0076688-3: SimpleLink Sub-1 GHz Ultra-Low Power Wireless Microcontroller, RGZ0048A (VQFN-48); Alternate PartNumber: CC1310F128RGZT; Manufacturer: Texas Instruments; CompType: IC; SizeArea_mm2: 49; Green_Lifecycle: Active; SizeAreaWB_mm2: 81; SizeZ_mm: 1; SizeY_mm: 7; Rating: Catalog; AEC Category: Q200; Green_REACh: Passed
Y1 = FC-135 32.7680KA-A3: Crystal, 32.768 KHz, 12.5 pF, SMD; Manufacturer: Epson; SymbolCreator: a0412235; U/M: EA; TaMin_C: -40; TaMax_C: 85; Frequency Stability: ±20ppm
Y2 = CMP-0004609-3: Crystal, 24 MHz, 9 pF, SMD; Manufacturer: Epson; TaMin_C: -40°C; TaMax_C: 85°C; Frequency Stability: +/-20ppm; Frequency_Fixed: 24MHz

## Sheet TIDA-00848-CoverSheet_E2.SchDoc
size A4; Date: Not shown in title block; ApprovedBy: Not shown in title block; CheckedBy: Not shown in title block; Author: Not shown in title block; CompanyName: Not shown in title block; Engineer: Not shown in title block; Organization: Not shown in title block; Address1: Not shown in title block; Address2: Not shown in title block; Address3: Not shown in title block; Address4: Not shown in title block; DocumentNumber: 1; Revision: Use project parameter SCH_Rev; SheetNumber: 1; SheetTotal: 3; PageSetup: Record=PageOptions¦CenterHorizontal=True¦CenterVertical=True¦PrintScale=1.00¦XCorrection=1.00¦YCorrection=1.00¦PrintKind=0¦BorderSize=5000000¦LeftOffset=0¦BottomOffset=0¦Orientation=2¦PaperLength=1000¦PaperWidth=1000¦Scale=100¦PaperSource=15¦PrintQuality=600¦MediaType=1¦DitherType=10¦PaperKind=Letter¦PrintScaleMode=1
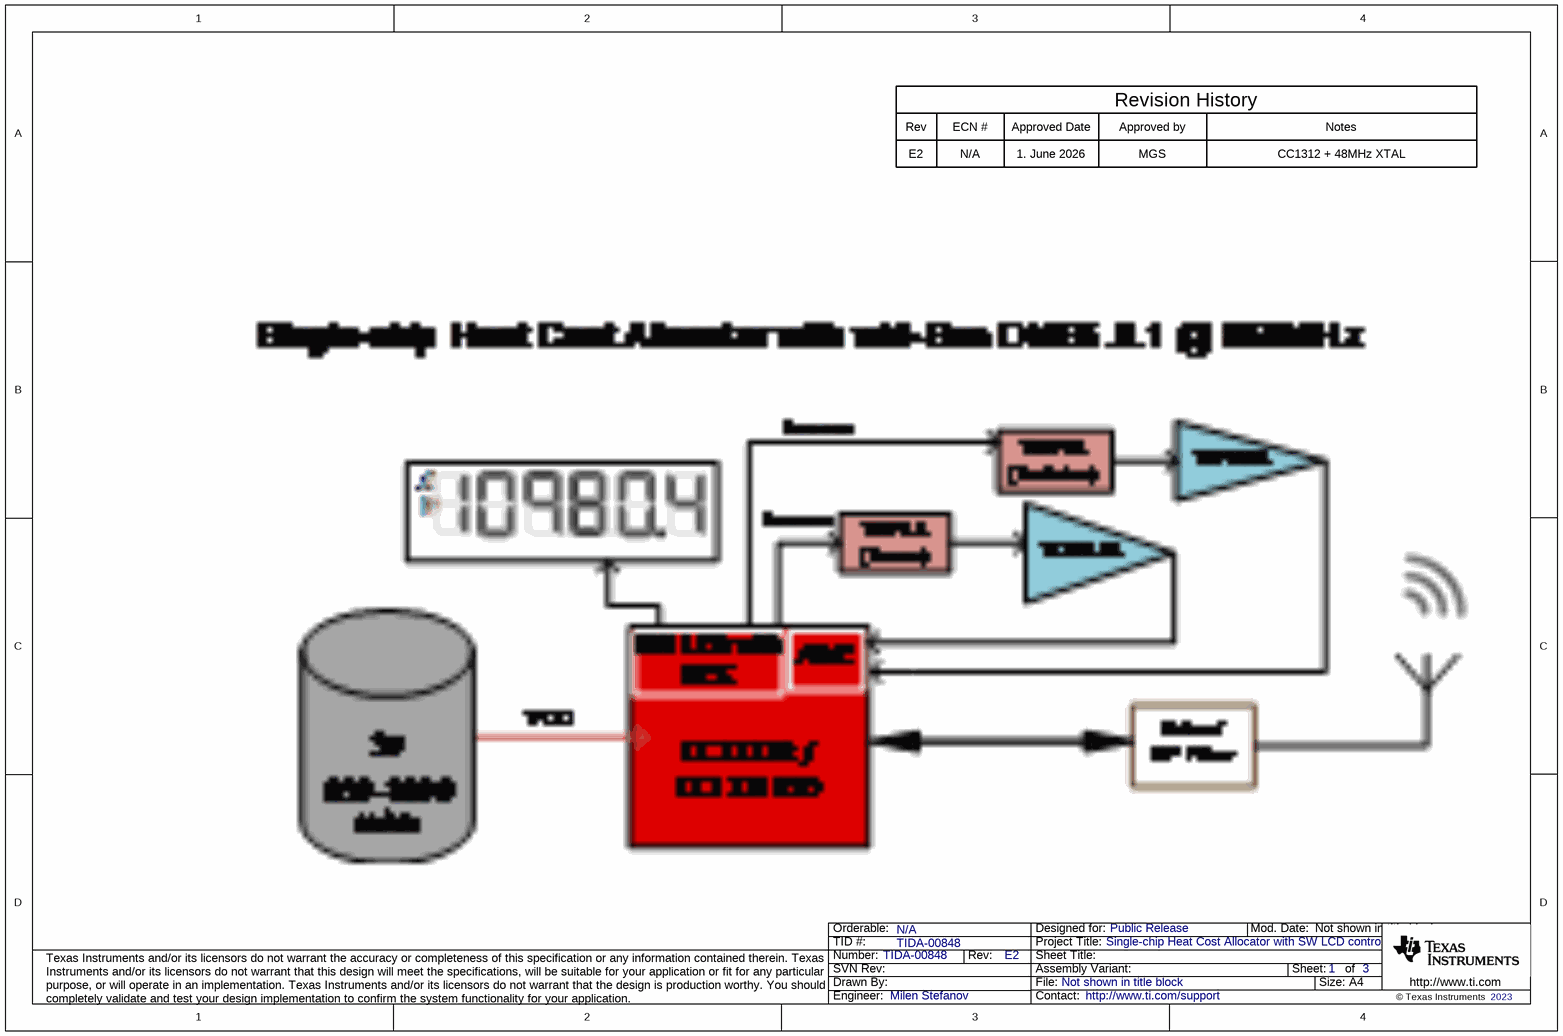
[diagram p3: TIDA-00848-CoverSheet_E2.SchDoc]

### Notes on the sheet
- Revision History
- Rev
- E2
- ECN #
- N/A
- Approved Date
- 1. June 2026
- Approved by
- MGS
- Notes
- CC1312 + 48MHz XTAL

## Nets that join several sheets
GND: TIDA-00848_LCD_E2 (6 pins), TIDA-00848_RF_E2 (34 pins)
VDDS: TIDA-00848_LCD_E2 (C41.1 J12.2 J13.1), TIDA-00848_RF_E2 (12 pins)
BASE_PWM: TIDA-00848_LCD_E2 (6 pins), TIDA-00848_RF_E2 (U5.39)
BASE_PWM_N: TIDA-00848_LCD_E2 (R29.2 U2.4), TIDA-00848_RF_E2 (J11.1 U5.40)
COM1_1: TIDA-00848_LCD_E2 (LCD1.25 R30.1 R30.2 R31.1), TIDA-00848_RF_E2 (U5.32)
COM2_1: TIDA-00848_LCD_E2 (LCD1.26 R32.1 R32.2 R33.1), TIDA-00848_RF_E2 (U5.36)
COM3_1: TIDA-00848_LCD_E2 (LCD1.27 R34.1 R34.2 R35.1), TIDA-00848_RF_E2 (U5.37)
COM4_1: TIDA-00848_LCD_E2 (LCD1.28 R36.1 R36.2 R37.1), TIDA-00848_RF_E2 (U5.38)
DIO_1: TIDA-00848_LCD_E2 (LCD1.15 R22.2), TIDA-00848_RF_E2 (U5.6)
DIO_2: TIDA-00848_LCD_E2 (J2.2 R25.2), TIDA-00848_RF_E2 (U5.7)
DIO_3: TIDA-00848_LCD_E2 (J3.2), TIDA-00848_RF_E2 (U5.8)
DIO_4: TIDA-00848_LCD_E2 (LCD1.13 R27.2), TIDA-00848_RF_E2 (U5.9)
DIO_5: TIDA-00848_LCD_E2 (LCD1.12 R4.1), TIDA-00848_RF_E2 (U5.10)
DIO_6: TIDA-00848_LCD_E2 (LCD1.11 R7.1), TIDA-00848_RF_E2 (U5.11)
DIO_7: TIDA-00848_LCD_E2 (LCD1.7 R13.1), TIDA-00848_RF_E2 (U5.12)
DIO_8: TIDA-00848_LCD_E2 (LCD1.10 R2.1), TIDA-00848_RF_E2 (U5.14)
DIO_10: TIDA-00848_LCD_E2 (LCD1.9 R1.1), TIDA-00848_RF_E2 (U5.16)
DIO_11: TIDA-00848_LCD_E2 (LCD1.21 R16.2), TIDA-00848_RF_E2 (U5.17)
DIO_12: TIDA-00848_LCD_E2 (LCD1.8 R14.1), TIDA-00848_RF_E2 (U5.18)
DIO_13: TIDA-00848_LCD_E2 (LCD1.22 R15.2), TIDA-00848_RF_E2 (U5.19)
DIO_14: TIDA-00848_LCD_E2 (LCD1.3 R3.1), TIDA-00848_RF_E2 (U5.20)
DIO_15: TIDA-00848_LCD_E2 (LCD1.2 R20.2), TIDA-00848_RF_E2 (U5.21)
DIO_18: TIDA-00848_LCD_E2 (LCD1.6 R10.1), TIDA-00848_RF_E2 (U5.28)
DIO_19: TIDA-00848_LCD_E2 (LCD1.24 R26.2), TIDA-00848_RF_E2 (U5.29)
DIO_20: TIDA-00848_LCD_E2 (LCD1.5 R9.1), TIDA-00848_RF_E2 (U5.30)
DIO_21: TIDA-00848_LCD_E2 (LCD1.4 R17.2), TIDA-00848_RF_E2 (U5.31)
JTAG_TDI: TIDA-00848_LCD_E2 (J21.2), TIDA-00848_RF_E2 (U5.27)
JTAG_TDO: TIDA-00848_LCD_E2 (J20.2), TIDA-00848_RF_E2 (U5.26)
LCD_PIN_20: TIDA-00848_LCD_E2 (LCD1.20 R18.2), TIDA-00848_RF_E2 (U5.15)
TDI: TIDA-00848_LCD_E2 (J21.3), TIDA-00848_RF_E2 (J4.8)
TDO: TIDA-00848_LCD_E2 (J20.1), TIDA-00848_RF_E2 (J4.6)

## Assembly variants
001: all parts fitted
002: not fitted C41 J9 J11 U2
